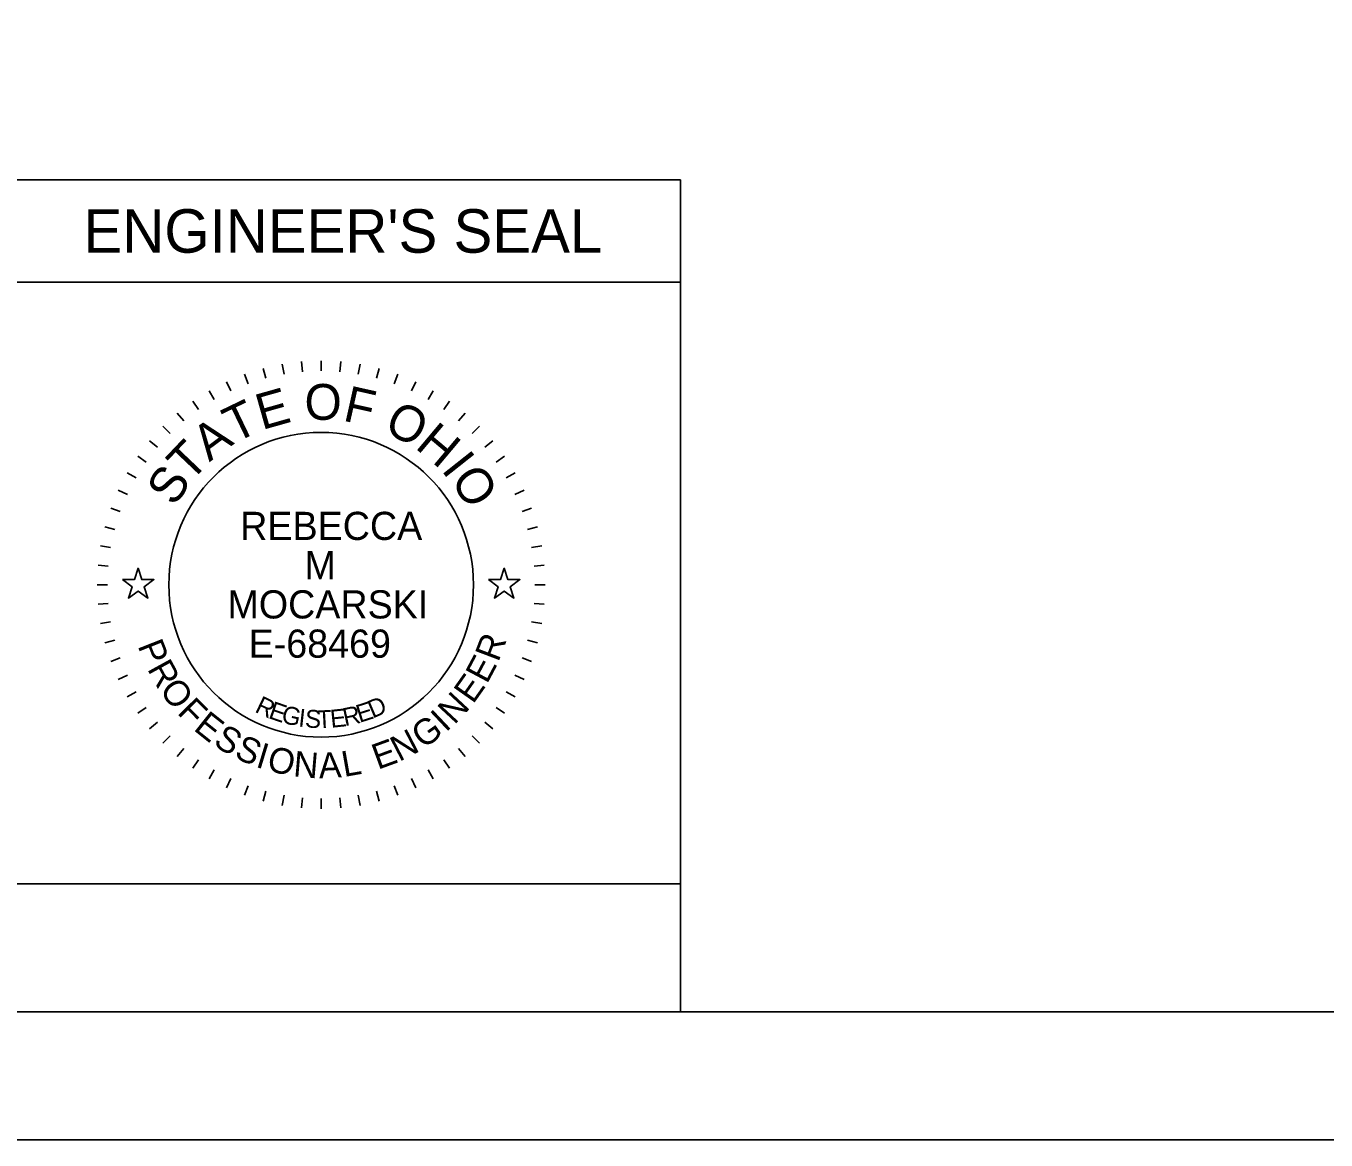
# Model space of a CAD drawing. Extents: x -6.4 to 34, y -4.2 to 22.
# Drawn here: x 23.84 to 28.92, y 0 to 4.35 of the extents above; entities that cross this region are included whole.
import ezdxf

# ---------------------------------------------------------------- set-up
doc = ezdxf.new("R2010")
doc.units = 0
for name, color, linetype in [('Default', 7, 'Continuous'), ('SH_Border', 7, 'Continuous'), ('SH_Cut_Line', 7, 'Continuous'), ('SH_Data', 7, 'Continuous')]:
    doc.layers.add(name, color=color, linetype=linetype)

msp = doc.modelspace()

# ---------------------------------------------------------------- linework, layer by layer
at = {"layer": 'Default'}
for points in [[(24.2198, 2.1883), (24.2666, 2.1883), (24.2811, 2.2329), (24.2956, 2.1883), (24.3425, 2.1883), (24.3046, 2.1607), (24.3191, 2.1161), (24.2811, 2.1437), (24.2432, 2.1161), (24.2576, 2.1607)], [(25.6498, 2.1883), (25.6966, 2.1883), (25.7111, 2.2329), (25.7256, 2.1883), (25.7725, 2.1883), (25.7346, 2.1607), (25.7491, 2.1161), (25.7111, 2.1437), (25.6732, 2.1161), (25.6876, 2.1607)]]:
    msp.add_lwpolyline(points, close=True, dxfattribs=at)
at = {"layer": 'SH_Border'}
msp.add_lwpolyline([(1.5, 21.5), (33.5, 21.5), (33.5, 0.5), (1.5, 0.5)], close=True, dxfattribs=at)
at = {"layer": 'SH_Cut_Line'}
msp.add_lwpolyline([(0, 0), (34, 0), (34, 22), (0, 22)], close=True, dxfattribs=at)
at = {"layer": 'SH_Data'}
for p, q in [((23.6, 3.75), (26.4, 3.75)), ((26.4, 3.75), (26.4, 0.5)), ((23.6, 3.35), (26.4, 3.35)), ((24.7697, 3.0135), (24.78, 2.9749)), ((24.8442, 3.03), (24.8511, 2.9906)), ((24.9199, 3.04), (24.9234, 3.0002)), ((24.9961, 3.0433), (24.9961, 3.0033)), ((25.0724, 3.04), (25.0689, 3.0002)), ((25.1481, 3.03), (25.1411, 2.9906)), ((25.2226, 3.0135), (25.2122, 2.9749)), ((24.6263, 2.9614), (24.6432, 2.9251)), ((24.6969, 2.9906), (24.7105, 2.953)), ((25.2954, 2.9906), (25.2817, 2.953)), ((25.3659, 2.9614), (25.349, 2.9251)), ((24.5586, 2.9261), (24.5786, 2.8915)), ((25.4336, 2.9261), (25.4136, 2.8915)), ((24.4943, 2.8851), (24.5172, 2.8523)), ((25.498, 2.8851), (25.4751, 2.8523)), ((24.4337, 2.8386), (24.4594, 2.808)), ((25.5586, 2.8386), (25.5329, 2.808)), ((24.3774, 2.7871), (24.4057, 2.7588)), ((25.6149, 2.7871), (25.5866, 2.7588)), ((24.3258, 2.7308), (24.3565, 2.7051)), ((25.6664, 2.7308), (25.6358, 2.7051)), ((24.2794, 2.6702), (24.3121, 2.6473)), ((25.7129, 2.6702), (25.6801, 2.6473)), ((24.2384, 2.6058), (24.273, 2.5858)), ((25.7539, 2.6058), (25.7193, 2.5858)), ((24.2031, 2.5381), (24.2394, 2.5212)), ((25.7892, 2.5381), (25.7529, 2.5212)), ((24.1739, 2.4676), (24.2115, 2.4539)), ((25.8184, 2.4676), (25.7808, 2.4539)), ((24.151, 2.3948), (24.1896, 2.3844)), ((25.8413, 2.3948), (25.8027, 2.3844)), ((24.1344, 2.3203), (24.1738, 2.3133)), ((25.8578, 2.3203), (25.8184, 2.3133)), ((24.1245, 2.2446), (24.1643, 2.2411)), ((25.8678, 2.2446), (25.828, 2.2411)), ((24.1211, 2.1683), (24.1611, 2.1683)), ((25.8711, 2.1683), (25.8311, 2.1683)), ((24.1245, 2.0921), (24.1643, 2.0956)), ((25.8678, 2.0921), (25.828, 2.0956)), ((24.1344, 2.0164), (24.1738, 2.0233)), ((25.8578, 2.0164), (25.8184, 2.0233)), ((24.151, 1.9419), (24.1896, 1.9522)), ((25.8413, 1.9419), (25.8027, 1.9522)), ((24.1739, 1.8691), (24.2115, 1.8827)), ((25.8184, 1.8691), (25.7808, 1.8827)), ((24.2031, 1.7985), (24.2394, 1.8154)), ((25.7892, 1.7985), (25.7529, 1.8154)), ((24.2384, 1.7308), (24.273, 1.7508)), ((25.7539, 1.7308), (25.7193, 1.7508)), ((24.2794, 1.6665), (24.3121, 1.6894)), ((25.7129, 1.6665), (25.6801, 1.6894)), ((24.3258, 1.6059), (24.3565, 1.6316)), ((25.6664, 1.6059), (25.6358, 1.6316)), ((24.3774, 1.5496), (24.4057, 1.5779)), ((25.6149, 1.5496), (25.5866, 1.5779)), ((24.4337, 1.498), (24.4594, 1.5287)), ((25.5586, 1.498), (25.5329, 1.5287)), ((24.4943, 1.4516), (24.5172, 1.4843)), ((25.498, 1.4516), (25.4751, 1.4843)), ((24.5586, 1.4106), (24.5786, 1.4452)), ((25.4336, 1.4106), (25.4136, 1.4452)), ((24.6263, 1.3753), (24.6432, 1.4116)), ((24.6969, 1.3461), (24.7105, 1.3837)), ((25.2954, 1.3461), (25.2817, 1.3837)), ((25.3659, 1.3753), (25.349, 1.4116)), ((24.7697, 1.3231), (24.78, 1.3618)), ((24.8442, 1.3066), (24.8511, 1.346)), ((24.9199, 1.2967), (24.9234, 1.3365)), ((24.9961, 1.2933), (24.9961, 1.3333)), ((25.0724, 1.2967), (25.0689, 1.3365)), ((25.1481, 1.3066), (25.1411, 1.346)), ((25.2226, 1.3231), (25.2122, 1.3618)), ((23.6, 0.5), (26.4, 0.5))]:
    msp.add_line(p, q, dxfattribs=at)
msp.add_lwpolyline([(23.6, 0.5), (23.6, 1), (26.4, 1), (26.4, 0.5)], close=True, dxfattribs=at)
msp.add_circle((24.9961, 2.1683), 0.595, dxfattribs=at)

# ---------------------------------------------------------------- texts
for s, height, p in [("ENGINEER'S SEAL", 0.17, (24.0676, 3.465)), ('REBECCA', 0.11, (24.6799, 2.3432)), ('M', 0.11, (24.9309, 2.19)), ('MOCARSKI', 0.11, (24.6301, 2.0367)), ('E-68469', 0.11, (24.7127, 1.8834))]:
    msp.add_text(s, height=height, dxfattribs=at).set_placement(p)
for s, height, rotation, p in [('O', 0.14, 359.7812, (24.9309, 2.8126)), ('E', 0.14, 15.7571, (24.7646, 2.7721)), ('F', 0.14, 347.4362, (25.0772, 2.8101)), ('T', 0.14, 25.7167, (24.6578, 2.7202)), ('O', 0.14, 332.2586, (25.236, 2.7698)), ('A', 0.14, 36.4747, (24.5595, 2.6464)), ('H', 0.14, 319.9136, (25.3593, 2.7044)), ('T', 0.14, 46.4344, (24.4844, 2.5648)), ('I', 0.14, 308.367, (25.4626, 2.6167)), ('S', 0.14, 57.1924, (24.4242, 2.4698)), ('O', 0.14, 303.1491, (25.4983, 2.5772)), ('P', 0.1, 291.494, (24.2784, 1.9304)), ('R', 0.1, 69.2322, (25.6881, 1.8637)), ('E', 0.1, 61.9951, (25.6438, 1.7782)), ('R', 0.1, 298.7311, (24.3151, 1.84)), ('O', 0.1, 306.4666, (24.3616, 1.7566)), ('E', 0.1, 54.758, (25.5895, 1.6997)), ('F', 0.1, 314.7068, (24.4304, 1.6666)), ('R', 0.07, 334.487, (24.7336, 1.6734)), ('D', 0.07, 23.3052, (25.1971, 1.6454)), ('N', 0.1, 47.0224, (25.5163, 1.6191)), ('E', 0.07, 341.04, (24.7868, 1.6484)), ('G', 0.07, 347.4752, (24.8376, 1.6301)), ('I', 0.07, 353.7858, (24.9052, 1.6151)), ('S', 0.07, 356.8926, (24.9319, 1.6112)), ('T', 0.07, 3.0061, (24.9818, 1.607)), ('E', 0.07, 6.0117, (25.0351, 1.6095)), ('R', 0.07, 11.9184, (25.0886, 1.6157)), ('E', 0.07, 17.6836, (25.1459, 1.6285)), ('I', 0.1, 43.287, (25.483, 1.5897)), ('E', 0.1, 321.4393, (24.4939, 1.6031)), ('G', 0.1, 35.0469, (25.3942, 1.5253)), ('S', 0.1, 328.6764, (24.5705, 1.5436)), ('S', 0.1, 335.9134, (24.6526, 1.4949)), ('N', 0.1, 27.3113, (25.3006, 1.4758)), ('I', 0.1, 343.1505, (24.7368, 1.458)), ('O', 0.1, 346.8859, (24.78, 1.4435)), ('E', 0.1, 20.0742, (25.2174, 1.4453)), ('N', 0.1, 355.1261, (24.885, 1.4201)), ('A', 0.1, 2.8617, (24.9884, 1.412)), ('L', 0.1, 10.0987, (25.0855, 1.4174))]:
    msp.add_text(s, height=height, rotation=rotation, dxfattribs=at).set_placement(p)

doc.saveas('drawing.dxf')
